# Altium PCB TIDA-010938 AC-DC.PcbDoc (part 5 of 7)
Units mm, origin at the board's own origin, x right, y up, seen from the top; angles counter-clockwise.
Board outline 275 x 170 mm, 4 copper layers (Top Layer, Layer 1, Layer 2, Bottom Layer), stack 1.787 mm thick; 711 components, 426 nets, 2196 pads, 1444 vias.
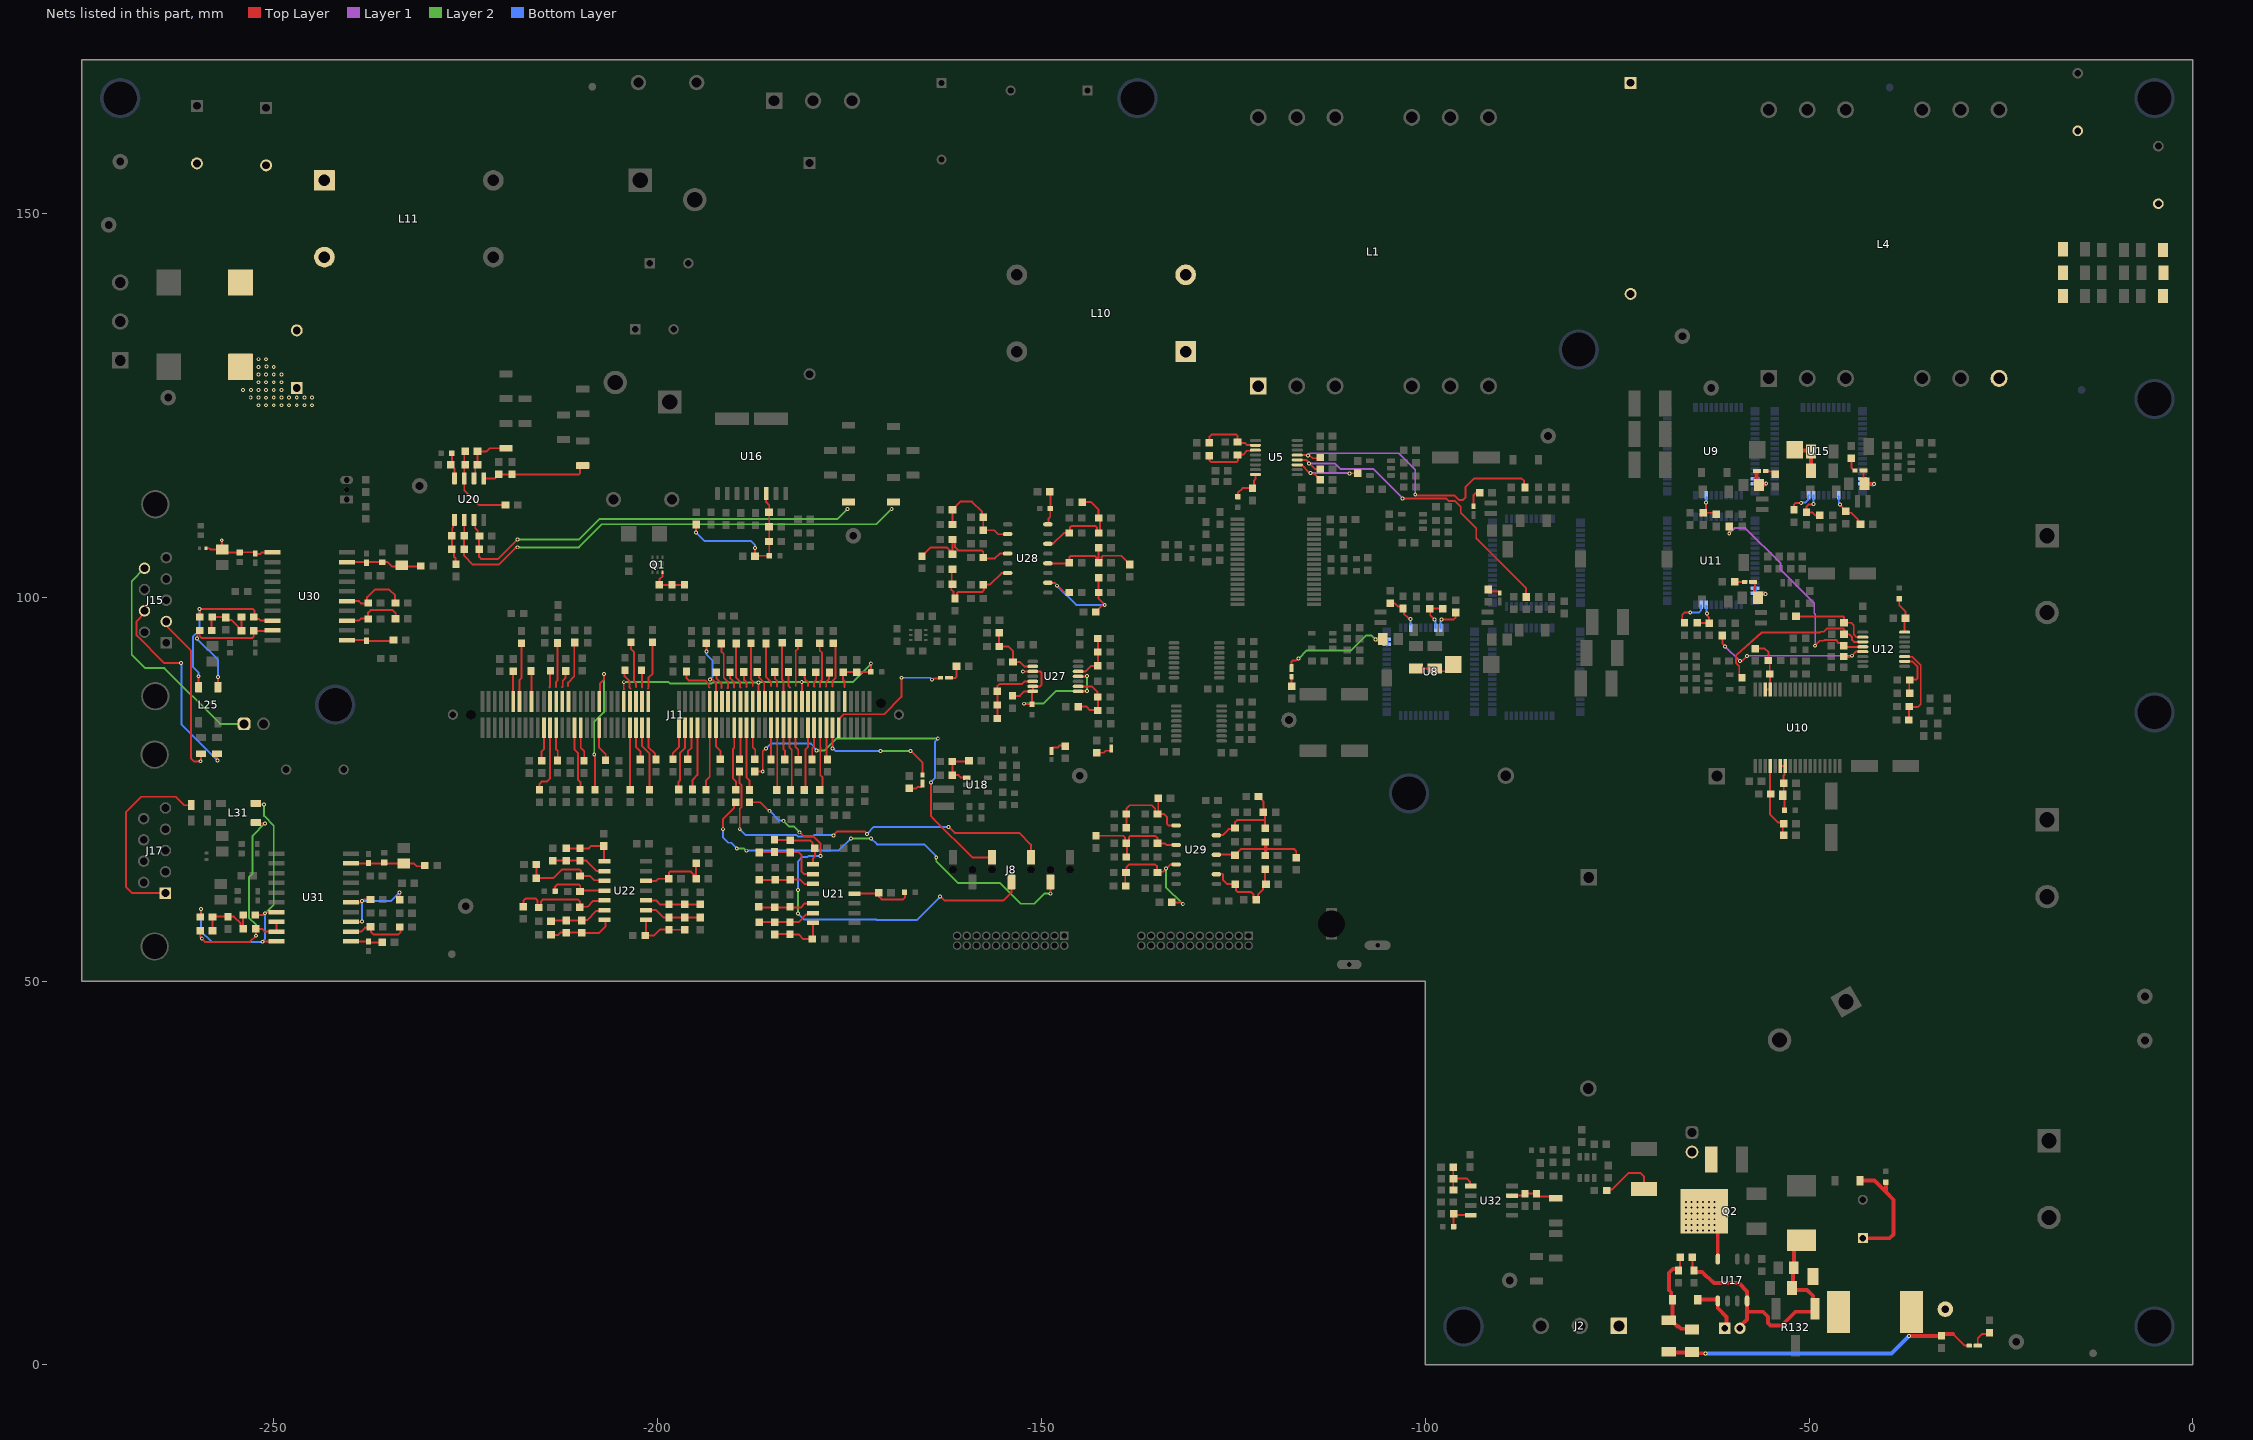
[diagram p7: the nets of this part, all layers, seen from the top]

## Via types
v1: diameter 0.508, hole 0.254, Top Layer to Bottom Layer, tented both sides, 1436 vias
v2: diameter 0.508, hole 0.254, Top Layer to Bottom Layer, 6 vias
v3: diameter 0.5, hole 0.2, Top Layer to Bottom Layer, 2 vias

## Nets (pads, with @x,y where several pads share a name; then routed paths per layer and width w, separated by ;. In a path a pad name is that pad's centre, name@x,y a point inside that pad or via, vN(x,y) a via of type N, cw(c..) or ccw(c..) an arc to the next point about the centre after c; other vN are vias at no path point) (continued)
NetC33_2: C33.2 R29.1 U5.3 | length 10
  Top Layer w0.25: U5.3@-116.675,117.248 -116.113,117.248 -115.095,116.23 -114.982,116.23 v1(-114.933,116.18) ; v1@-114.95,116.163 -114.918,116.131 -114.531,116.131 C33.2@-113.65,115.25 ; v1@-109.75,116.05 -109.65,116.15 R29.1@-108.8,116.15
  Layer 1 w0.25: v1(-114.933,116.18) -114.905,116.153 -109.878,116.153 v1(-109.85,116.125)
NetC34_2: C34.2 R27.1 U5.4 | length 40.7
  Top Layer w0.25: U5.4@-116.675,117.883 -115.533,117.883 -114.375,116.725 -114,116.725 C34.2@-113.9,116.625 ; v1(-102.975,112.875) -102.946,112.846 -97.246,112.846 -96.95,112.55 -96.127,112.55 -95.371,111.794 -95.371,110.971 -93.35,108.95 -93.35,107.675 -86.85,101.175 R27.1@-86.85,100.025
  Layer 1 w0.25: v1(-115.15,117.4) -111.723,117.4 -111.044,116.721 -110.606,116.721 -110.602,116.725 -106.775,116.725 -102.975,112.925 v1(-102.975,112.875)
NetC35_2: C35.2 R25.1 U5.5 | length 38.8
  Top Layer w0.25: U5.5@-116.675,118.518 -115.093,118.518 -114.675,118.1 -113.85,118.1 C35.2@-113.825,118.075 ; v1(-101.3,113.375) -101.23,113.375 -101.101,113.246 -96.18,113.246 -95.605,112.671 -95.081,112.671 -94.771,112.981 -94.771,114.329 -93.65,115.45 -87.425,115.45 -87.125,115.15 -87.125,114.275 R25.1@-86.975,114.125
  Layer 1 w0.25: v1(-115.25,118.475) -114.975,118.75 -103.45,118.75 -101.3,116.6 v1(-101.3,113.375)
NetC38_1: C38.1 FB3.2 U5.16 | length 4.6
  Top Layer w0.25: FB3.2@-124.4,113.1 -124.4,113.6 -123.8,114.2 C38.1@-122.5,114.2 -122.3,114.4 -122.3,115.2 -122.125,115.375 -122.125,115.525 U5.16@-122.125,115.978
NetC41_2: C41.2 R22.2 U5.11 | length 7.3
  Top Layer w0.25: R22.2@-128.1,118.2 -128.1,117.8 -127.925,117.625 -124.546,117.625 -124.4,117.771 -124.4,118.525 -124.352,118.574 -123.721,118.574 -123.22,119.075 U5.11@-122.35,119.075
NetC42_2: C42.2 R20.2 U5.10 | length 7.4
  Top Layer w0.25: R20.2@-128.125,120.45 -128.125,120.875 -127.825,121.175 -124.596,121.175 -124.45,121.029 C42.2@-124.45,120.225 ; C42.2@-124.35,120.075 -123.45,120.075 -123.191,119.816 -122.154,119.816 U5.10@-122.125,119.788
NetC45_1: C45.1 R109.1 R118.2 U20.3 | length 55.9
  Top Layer w0.25: U20.3@-223.915,110.075 -223.75,109.91 -223.75,109 -223.429,108.679 -223.429,108.104 -223.25,107.925 C45.1@-223.25,106.25 -223.25,105.25 -223,105 -220.75,105 v1(-218.25,107.5)
  Layer 2 w0.25: v1(-218.25,107.5) -210.25,107.5 -207.547,110.203 -176.547,110.203 v1(-175.25,111.5)
NetC50_2: C50.2 U8.51 | length 3.8
  Top Layer w0.25: v1(-97.875,97.1) -96.3,97.1 -96.05,97.35 -96.05,98.025 C50.2@-96.075,98.05
  Bottom Layer w0.25: U8.51@-98.008,96 -98.008,96.897 -97.875,97.03 v1(-97.875,97.1)
NetC51_2: C51.2 R35.2 U8.45 | length 4.5
  Top Layer w0.25: R35.2@-104.575,99.225 -104.525,99.175 -103.925,99.175 -103.575,98.825 -103.575,98.8 -103.225,98.8 C51.2@-103,98.575 ; C51.2@-102.9,98.525 -102.775,98.4 -102.775,97.85 -102.175,97.25 -102.07,97.25 -102.019,97.199 -101.976,97.199 v1@-101.925,97.25
  Bottom Layer w0.25: U8.45@-101.925,96.425 -101.9,96.45 v1(-101.9,97.15)
NetC53_2: C53.2 R40.2 U8.50 | length 4.6
  Top Layer w0.25: v1@-98.775,97.125 -98.8,97.125 -99.35,97.675 -99.35,98.45 R40.2@-99.4,98.5 C53.2@-97.7,98.5 -97.65,98.5 C53.2@-97.6,98.55
  Bottom Layer w0.25: v1@-98.75,97.075 -98.75,97.005 -98.658,96.913 U8.50@-98.658,96
  other v1: -98.775,97.1
NetC54_1: C54.1 D25.1 U8.40 U8.41 | length 16.2
  Top Layer w0.25: D25.1@-117.4,90.77 -117.4,91.646 -117.275,91.771 -116.799,91.771 -116.57,92 v1(-116.5,92)
  Top Layer w0.5: v1@-106.425,94.525 -106.4,94.55 C54.1@-105.541,94.55 C54.1@-105.241,94.55
  Layer 2 w0.25: v1(-116.5,92) -115.429,93.071 -109.646,93.071 -107.717,95 -106.975,95 v1(-106.475,94.5)
  Bottom Layer w0.5: v1@-106.325,94.5 U8.41@-105.343,94.5 ; U8.40@-105.018,93.85 U8.41@-105.018,94.475
NetC55_1: C55.1 FB11.2 U27.1 U27.4 U27.10 U27.13 U27.14 | length 24.3
  Top Layer w0.25: C55.1@-153.76,87.143 -152.807,87.143 -152.217,87.733 -151.592,87.733 U27.14@-151.575,87.75 ; v1@-152.425,90.3 -152.392,90.333 -150.146,90.333 -150,90.187 -150,88.529 -150.146,88.383 U27.13@-151.119,88.383 U27.14@-151.119,87.733 -151.125,87.733 -151.217,87.641 FB11.2@-151.217,86.167 ; v1@-152.25,86.05 -152.235,86.065 FB11.2@-151.217,86.065 ; U27.1@-145.219,87.733 -145.211,87.725 v1@-144.075,87.725 ; U27.4@-145.219,89.683 -144.058,89.683 v1@-144.05,89.675
  Layer 2 w0.25: v1(-152.275,86.125) -149.748,86.125 -148.073,87.8 v1(-144.075,87.8) ; v1@-144.1,87.7 -144.062,87.738 -144.062,89.713 v1(-144.05,89.725)
  other v1: -152.425,90.325
NetC60_2: C60.2 R44.2 U9.50 | length 4.3
  Top Layer w0.25: C60.2@-63.9,111.2 -63.625,111.2 -63.45,111.375 v1@-63.45,112.2 ; v1@-63.525,112.25 v1@-63.462,112.188 ; C60.2@-63.5,110.7 C60.2@-63.8,111 -62.4,111 R44.2@-62.2,110.8
  Bottom Layer w0.25: v1@-63.37,112.3 -63.378,112.307 -63.378,112.922 U9.50@-63.3,113
  other v1: -63.45,112.325
NetC61_1: C61.1 D26.1 U9.40 U9.41 | length 5
  Top Layer w0.5: D26.1@-56.8,116.4 -56.84,116.4 -56.84,114.795 -56.909,114.725 -56.859,114.675 -55.802,114.675 -55.677,114.8 v1@-55.675,114.8
  Bottom Layer w0.5: U9.41@-57.025,114.775 -55.75,114.775 v1@-55.7,114.725 ; U9.40@-57.025,115.425 -57,115.425 -56.975,115.4 U9.41@-56.975,114.875
  other v1: -55.575,114.8
NetC64_2: C64.2 C67.1 FB4.2 U10.6 U10.7 | length 6.6
  Top Layer w0.25: U10.6@-53.775,78.025 -53.225,78.025 U10.7@-53.175,77.975 ; C64.2@-53.425,74.2 -53.2,73.975 FB4.2@-53.2,72.25 ; C67.1@-53.325,75.75 -53.325,76.75 -53.175,76.9 U10.7@-53.175,77.975 ; C64.2@-53.3,74.2 C67.1@-53.3,75.75 ; U10.7@-53.125,78.025 U10.7@-53.175,77.975
NetC66_1: C66.1 R45.2 R49.1 U10.33 U10.34 | length 7.2
  Top Layer w0.25: R49.1@-57,93.3 -55.775,93.3 -55.275,92.8 R45.2@-55.275,91.9 ; U10.34@-55.725,87.975 U10.33@-55.175,87.975 ; R45.2@-55.3,91.675 -55.125,91.5 C66.1@-55.125,90 ; U10.33@-55.075,87.975 C66.1@-55.075,90
NetC68_2: C68.2 R46.2 R48.2 U10.4 | length 10.1
  Top Layer w0.25: U10.4@-55.075,78.025 -55.075,74.35 -55.075,71.675 -54.029,70.629 -53.554,70.629 R46.2@-53.425,70.499 ; R48.2@-53.425,68.95 -53.425,70.375 R46.2@-53.325,70.475
NetC70_2: C70.2 U11.51 | length 4.4
  Top Layer w0.25: C70.2@-66.525,96.65 -66.525,97.725 -66.25,98 -65.55,98 v1@-65.5,98.05
  Bottom Layer w0.25: v1(-65.475,98) -64.375,98 -64.075,98.3 -64.075,98.9 U11.51@-64.05,98.925
NetC72_2: C72.2 R60.2 U11.50 | length 4.1
  Top Layer w0.25: C72.2@-64.775,96.65 R60.2@-63.05,96.65 ; v1(-63.3,97.875) -63.275,97.85 -63.275,97.6 -63.05,97.375 R60.2@-63.05,96.675
  Bottom Layer w0.25: U11.50@-63.425,98.875 -63.343,98.793 -63.343,97.918 v1(-63.3,97.875)
NetC73_1: C73.1 D27.1 U11.40 U11.41 | length 4.1
  Top Layer w0.25: D27.1@-57.03,102 -57.03,100.73 C73.1@-57,100.7
  Top Layer w0.5: C73.1@-56.859,100.425 v1(-55.7,100.425)
  Bottom Layer w0.5: U11.41@-57.025,100.6 U11.40@-57.025,101.175 ; U11.41@-56.7,100.5 -55.777,100.5 -55.702,100.425 v1(-55.7,100.425)
NetC74_2: C74.2 R36.2 R110.1 U32.3 | length 5.7
  Top Layer w0.25: U32.3@-88.606,22.104 U32.3@-88.675,22.035 -87.265,22.035 C74.2@-87,22.3 R110.1@-85.5,22.3 -85.5,22.275 -85.15,21.925 -83.825,21.925 R36.2@-83.5,21.6
NetC75_1: C75.1 R124.2 R130.2 U20.6 | length 7.6
  Top Layer w0.25: U20.6@-223.915,115.475 -223.75,115.64 -223.75,116.95 R130.2@-223.45,117.25 C75.1@-223.45,119 -222.25,119 -221.85,119.4 R124.2@-219.75,119.4
NetC75_2: C75.2 R120.1 R130.1 U20.7 | length 11.3
  Top Layer w0.25: C75.2@-225.185,119 U20.7@-225.185,115.475 -225.185,113.935 -223.25,112 R120.1@-219.8,112
NetC77_2: C77.2 R59.1 U12.5 | length 21.7
  Top Layer w0.25: R59.1@-61.3,95 -61.3,93.971 v1@-60.929,93.6 ; v1@-59.025,91.675 -58.75,91.675 v1(-58.075,92.35) ; C77.2@-45.375,92.225 -44.672,92.225 -44.522,92.375 v1(-44.425,92.375) -43.895,92.905 U12.5@-43,92.905
  Layer 1 w0.25: v1@-61,93.575 v1(-60.95,93.575) -60.9,93.575 -59.025,91.7 v1(-58.975,91.7) ; v1@-57.975,92.375 -44.525,92.375 v1@-44.5,92.4
NetC78_2: C78.2 R62.1 U12.4 | length 28.8
  Top Layer w0.25: v1(-60.4,108.3) R62.1@-60.4,109.2 ; v1@-49.15,93.775 -48.596,94.329 -48.073,94.329 -47.977,94.425 -46.486,94.425 -46.325,94.264 -46.325,94.17 -46.179,94.023 -45.848,94.023 -45.35,93.525 U12.4@-43.3,93.525
  Layer 1 w0.25: v1(-60.4,108.3) -59.7,109 -58.3,109 -53.7,104.4 -53.7,103.566 -49.325,99.191 -49.325,97.925 -49.2,97.8 v1@-49.2,93.766
  other v1: -49.25,93.675
NetC79_2: C79.2 R64.1 U12.3 | length 21.7
  Top Layer w0.25: R64.1@-59,89.7 -59.1,89.8 -59.1,91 -59.504,91.404 -59.504,91.919 -59.5,91.923 -59.5,92.3 -59.499,92.401 -59.423,92.477 -56.194,95.4 -48.6,95.4 -48.5,95.5 -48.089,95.5 -47.664,95.925 -46.436,95.925 -45.571,95.925 -45.4,95.754 -45.4,95.225 C79.2@-45.45,95.175 ; C79.2@-45.322,95.047 C79.2@-45.45,95.175 ; -44.125,94.175 -44.419,94.469 -44.419,94.819 -44.775,95.175 C79.2@-45.45,95.175 ; -44.106,94.179 -43.654,94.179 U12.3@-43.625,94.15
NetC80_2: C80.2 R66.1 U12.2 | length 10.4
  Top Layer w0.25: R66.1@-51.7,97.5 -45.55,97.5 -45.451,97.401 -45.451,96.701 C80.2@-45.3,96.55 ; C80.2@-45.3,96.675 -44.475,96.675 -44.175,96.375 -44.175,95.15 -43.839,94.814 -43.561,94.814 U12.2@-43.55,94.825
NetC81_1: C81.1 R129.2 R131.2 U20.2 | length 63.9
  Top Layer w0.25: U20.2@-225.185,110.075 -225.185,108.015 R131.2@-225.2,108 C81.1@-225.2,106.25 -225.2,105.396 -224.054,104.25 -220.684,104.25 -218.484,106.451 -218.299,106.451 v1(-218.25,106.5)
  Layer 2 w0.25: v1(-218.25,106.5) -210.25,106.5 -207.25,109.5 -171.5,109.5 v1(-169.5,111.5)
NetC81_2: C81.2 R121.1 R131.1 U20.1 | length 6.1
  Top Layer w0.25: U20.1@-226.455,110.075 -226.63,109.9 -226.63,109.12 -226.75,109 -226.75,108.05 R131.1@-226.8,108 C81.2@-226.8,106.25 -226.5,105.95 -226.5,105.25 -226.3,105.05 -226.3,104.35 R121.1@-226.25,104.3
NetC84_1: C84.1 FB5.2 U12.16 | length 4.4
  Top Layer w0.25: FB5.2@-38.25,99.8 -38.25,98.95 -37.45,98.15 C84.1@-37.45,97.65 ; U12.16@-37.5,95.4 -37.55,95.45 -37.55,97.15 C84.1@-37.45,97.25
NetC86_2: C86.2 R56.2 U12.11 | length 11.2
  Top Layer w0.25: U12.11@-37.55,92.27 -37.521,92.241 -36.576,92.241 -35.45,91.116 -35.45,86.025 -35.775,85.7 -36.825,85.7 C86.2@-36.975,85.55 ; R56.2@-37,84 -37,85.8 C86.2@-36.975,85.825
NetC87_2: C87.2 R54.2 U12.10 | length 6.5
  Top Layer w0.25: U12.10@-37.55,91.635 -36.535,91.635 -35.85,90.95 -35.85,89.446 -35.996,89.3 C87.2@-36.975,89.3 ; R54.2@-36.95,87.35 -36.95,89.15 C87.2@-36.9,89.2
NetC93_2: C93.2 R38.2 R252.2 U27.2 | length 7.5
  Top Layer w0.25: U27.2@-145.219,88.383 -143.433,88.383 -142.7,87.65 -142.7,87.275 R252.2@-142.675,87.25 ; C93.2@-145.21,85.738 -144.113,85.738 -143.675,85.3 -142.925,85.3 R38.2@-142.9,85.275 ; R252.2@-142.646,87.008 -142.646,85.271 R38.2@-142.625,85.25
NetC95_2: C95.2 U15.51 | length 3.9
  Top Layer w0.152: v1@-51.093,112.207 v1(-51.025,112.275)
  Top Layer w0.25: C95.2@-51.975,111.075 -51.95,111.1 -51.95,112.075 -51.75,112.275 -51.075,112.275 v1@-51.05,112.3
  Bottom Layer w0.152: v1(-51.025,112.275) v1@-51.007,112.293
  Bottom Layer w0.25: v1@-51.05,112.25 -50.976,112.324 -50.476,112.324 -50.135,112.666 -50.135,113.175 U15.51@-50.035,113.275
NetC96_2: C96.2 R69.2 U15.45 | length 5.3
  Top Layer w0.25: v1(-45.95,112.05) -45.95,111.98 -45.373,111.404 -45.373,111.05 -45.348,111.025 C96.2@-45.3,111.025 ; C96.2@-45.225,111.175 -45.05,111 -44.5,111 -43.653,110.153 -43.653,109.85 -43.303,109.5 R69.2@-43.3,109.5
  Bottom Layer w0.152: U15.45@-46.225,113.125 U15.45@-46.213,113.113
  Bottom Layer w0.25: U15.45@-46.2,113.125 -46.135,113.06 -46.135,112.305 -45.95,112.12 v1(-45.95,112.05)
NetC97_2: C97.2 R74.2 U15.50 | length 5
  Top Layer w0.152: R74.2@-49.024,110.425 -49,110.449 R74.2@-49,110.475
  Top Layer w0.25: v1@-49.45,112.15 -49.504,112.096 -50.054,112.096 -50.325,111.825 C97.2@-50.325,111.05 -49.6,111.05 -49.2,110.65 -48.65,110.65 R74.2@-48.625,110.625
  Bottom Layer w0.25: U15.50@-49.385,113.275 -49.405,113.255 -49.405,112.08 v1@-49.375,112.05
  other v1: -49.425,112.125
NetC99_1: C99.1 D28.1 U15.40 U15.41 | length 4.7
  Top Layer w0.25: C99.1@-42.9,115.1 D28.1@-42.9,116.5
  Top Layer w0.5: C99.1@-42.784,114.775 -41.525,114.775 v1@-41.5,114.8
  Bottom Layer w0.5: U15.40@-43.025,115.4 U15.41@-43.025,114.775 -41.8,114.775 v1@-41.725,114.7
  other v1: -41.55,114.75
NetC100_2: C100.2 R67.2 R255.2 U27.5 | length 6.3
  Top Layer w0.25: U27.5@-145.219,90.333 -144.242,90.333 -143.55,91.025 R255.2@-142.725,91.025 ; R255.2@-142.646,91.072 C100.2@-142.646,92.85 R67.2@-142.646,94.628
NetC101_2: C101.2 R72.2 R256.2 U27.9 | length 7.5
  Top Layer w0.25: C101.2@-155.55,93.875 -155.55,95.302 R72.2@-155.487,95.365 ; C101.2@-155.487,93.587 -154.312,93.587 -153.725,93 R256.2@-153.725,91.555 ; R256.2@-153.709,91.555 -152.777,91.555 -152.205,90.983 -151.458,90.983 U27.9@-151.45,90.975
NetC103_1: C103.1 C244.1 L4.6 L10.4 R291.1 R326.1 R327.1
NetC103_2: C103.2 C243.2 L1.1 L10.1 R77.2 R79.2 R80.2
NetC109_1: C109.1 C110.1 C111.1 FB6.2 R84.1 R85.1 U16.8 | length 20.9
  Top Layer w0.25: R84.1@-194.978,109.479 -194.978,108.478 v1@-194.975,108.475 ; v1@-187.3,106.4 -187.308,106.392 R85.1@-187.308,105.34 -187.248,105.4 -185.675,105.4 -185.6,105.325 FB6.2@-185.6,105.25 ; U16.8@-185.845,113.516 -185.875,113.486 -185.875,112.4 -185.45,111.975 -185.45,105.45 FB6.2@-185.525,105.375
  Bottom Layer w0.25: v1(-195,108.45) -193.85,107.3 -187.8,107.3 -187.325,106.825 v1@-187.325,106.575
  other v1: -187.325,106.425
NetC114_1: C114.1 Q1.3 R89.2 R90.1 | length 5.1
  Top Layer w0.25: C114.1@-199.75,101.6 R90.1@-198.125,101.6 R89.2@-196.5,101.6 R89.2@-196.4,101.6 ; C114.1@-199.75,101.675 -199.725,101.7 -199.725,102.375 -199.35,102.75 Q1.3@-199.35,103.275
NetC116_1: C116.1 D14.1 U17.1 | length 6.7
  Top Layer w0.5: D14.1@-64.399,8.5 -61.935,8.5 U17.1@-61.889,8.454 ; U17.1@-61.889,8.327 -61.889,7.389 -60.75,6.25 -60.75,5 C116.1@-61,4.75
NetC116_2: C116.2 C117.2 D20.1 L13.1 R95.1 R97.2 R98.2 R132.1 TP23.1 U17.4 | length 37.9
  Top Layer w0.25: C117.2@-65.2,14 -65.2,12.3 R95.1@-65,12.1
  Top Layer w0.5: R95.1@-65.1,12.1 -63.93,12.1 -63.783,11.954 -63.76,11.931 ccw(c-61.889,13.352) -63.071,11.321 -63.027,11.277 -62.4,10.65 -59.15,10.65 -58.079,9.579 U17.4@-58.079,8.327 -58.079,6.915 -58.079,6.012 ; C116.2@-59,4.75 C116.2@-59,4.971 ; C116.2@-59,5.021 -58.044,5.977 ; -58.079,6.821 -57.985,6.915 -55.99,6.915 -55.346,6.271 -55.346,5.443 -55.023,5.12 -53.557,5.12 -51.762,6.915 -49.21,6.915 -49.5,7.205 -49.5,9 -50.25,9.75 -52.2,9.75 -52.092,9.858 -52.092,12.392 -51.984,12.5 -51.984,14.947 D20.1@-51,15.931
NetC117_1: C117.1 D14.2 D15.1 R93.2 R94.1 | length 13.1
  Top Layer w0.25: R93.2@-67,12.5 -66.975,12.5 -66.8,12.675 C117.1@-66.8,14
  Top Layer w0.5: D15.1@-68.25,5.79 D15.1@-68.145,5.79 ; R93.2@-67,12.5 -67.75,12.5 -68.25,12 -68.25,9.75 -67.952,9.452 -67.952,8.677 D14.2@-67.775,8.5 -67.775,6.16 D15.1@-68.145,5.79 ; R94.1@-65.25,4.7 -66.7,4.7 -67,5 -67.135,5 -67.925,5.79 D15.1@-68.145,5.79
NetC118_1: C118.1 C119.1 D15.2 D16.2 D19.1 FB15.1 L13.2 R94.2 TP20.1 | length 56.4
  Top Layer w0.25: -31.25,4 -29.75,2.5 D16.2@-29.145,2.5
  Top Layer w0.5: D15.2@-68.25,1.71 -68.153,1.613 -65.437,1.613 -65.25,1.8 -64.952,1.502 -63.502,1.502 v1(-63.5,1.5) ; D19.1@-43.362,24 -41.5,24 -40,22.5 ; C118.1@-43,16.5 -39.5,16.5 -39,17 -39,21.5 -40,22.5 ; FB15.1@-40,23.8 -40,22.5 ; v1(-37,3.75) -36.998,3.752 -32.798,3.752 C119.1@-32.75,3.8 -32.55,4 -31.25,4
  Bottom Layer w0.5: v1(-63.5,1.5) -39.25,1.5 v1(-37,3.75)
NetC127_2: C127.2 R104.2 R107.2 U18.1 | length 5.6
  Top Layer w0.25: U18.1@-160,76.525 -160.525,76.525 -160.819,76.819 C127.2@-161.597,76.819 R107.2@-161.597,78.597 -159.578,78.597 R104.2@-159.55,78.625
NetC128_2: C128.2 FB12.2 U32.8 | length 3.5
  Top Layer w0.25: FB12.2@-96.3,18 C128.2@-96.3,19.675 -96.12,19.495 -94.545,19.495 U32.8@-94.525,19.475
NetC129_1: C129.1 R108.1 R113.2 U20.5 | length 14
  Top Layer w0.25: U20.5@-222.645,115.475 -221.175,115.475 -220.65,116 R108.1@-218.95,116 -210.25,116 -210.104,116.146 -210.104,116.825 -209.779,117.15 R113.2@-209.75,117.15
NetC139_2: C139.2 R133.2 R135.1 U32.5 | length 5.8
  Top Layer w0.25: R133.2@-96.35,25.75 -96.35,22.975 C139.2@-96.225,22.85 ; R135.1@-96.325,24.25 -94.55,24.25 -94.175,23.875 -94.175,23.475 U32.5@-94.1,23.4
NetC141_2: C141.2 FB7.2 U21.4 | length 7.8
  Top Layer w0.25: U21.4@-174.347,61.387 -171.463,61.387 C141.2@-171.45,61.4 ; C141.2@-171.195,61.512 -171.15,61.467 -171.15,60.946 -170.829,60.625 -168.025,60.625 -167.75,60.9 -167.75,61.5 FB7.2@-167.725,61.525
NetC142_2: C142.2 FB8.2 U22.4 | length 7.6
  Top Layer w0.25: FB8.2@-213.244,61.65 -213.35,61.756 -213.35,62.3 -213.075,62.575 -210.25,62.575 -210.075,62.4 C142.2@-210.075,61.975 ; C142.2@-210.096,61.65 -209.971,61.775 -207.2,61.775 U22.4@-207.175,61.8
NetC143_2: C143.2 R136.1 R139.2 U22.3 | length 11.3
  Top Layer w0.25: R136.1@-215.797,63.395 -213.589,63.395 -212.433,64.55 -210.175,64.55 -210,64.375 C143.2@-210,63.925 ; R139.2@-215.797,65.173 -215.775,65.151 R136.1@-215.775,63.625 ; C143.2@-210.096,63.682 -208.832,63.682 -208.275,63.125 -207.425,63.125 U22.3@-207.4,63.15
NetC148_1: C148.1 R143.2 R145.2 U22.2 | length 7
  Top Layer w0.25: R143.2@-213.657,65.676 -213.656,65.675 C148.1@-210.225,65.675 ; C148.1@-210.101,65.676 -209.276,65.676 -207.925,64.325 U22.2@-207.125,64.325
NetC148_2: C148.2 R141.1 R145.1 U22.1 | length 6.7
  Top Layer w0.25: R145.1@-211.879,67.276 -211.853,67.25 C148.2@-210.101,67.25 ; C148.2@-210.101,67.276 -208.949,67.276 -208.625,67.6 -207.25,67.6 R141.1@-207.125,67.475 ; U22.1@-207,65.775 -206.998,65.777 R141.1@-206.998,67.475
NetC150_1: C150.1 R147.2 R149.1 U22.5 | length 13.1
  Top Layer w0.25: R149.1@-217.5,59.694 -217.475,59.719 -217.475,60.425 -217.15,60.75 -215.875,60.75 -215.65,60.525 -215.65,59.975 R147.2@-215.675,59.95 ; R147.2@-215.325,59.775 -215.175,59.925 -215.175,60.375 -214.925,60.625 -210.375,60.625 -210.1,60.35 C150.1@-210.1,59.925 ; C150.1@-210.134,59.618 -210.077,59.675 -209.125,59.675 -208.35,60.45 -207.3,60.45 U22.5@-207.2,60.55
NetC154_1: C154.1 R153.1 R155.1 U22.6 | length 7.7
  Top Layer w0.25: R153.1@-214.15,57.775 -214.047,57.878 C154.1@-209.88,57.878 -209.834,57.924 -209.176,57.924 -207.975,59.125 U22.6@-206.975,59.125
NetC154_2: C154.2 R151.1 R155.2 U22.7 | length 8.2
  Top Layer w0.25: R151.1@-213.873,56.02 -212.93,56.02 -212.65,56.3 C154.2@-209.95,56.3 ; C154.2@-209.88,56.278 -207.622,56.278 -206.775,57.125 U22.7@-206.775,57.8
NetC155_2: C155.2 R156.1 R159.2 U22.10 | length 7.2
  Top Layer w0.25: U22.10@-201.504,60.505 -200.205,60.505 -199.65,59.95 R159.2@-194.525,59.95
NetC156_1: C156.1 R157.2 R158.1 U21.10 | length 7.2
  Top Layer w0.25: R158.1@-186.769,63.181 -184.737,63.181 -182.856,63.181 C156.1@-182.8,63.125 ; C156.1@-182.675,63.3 -182.575,63.2 -181.425,63.2 -180.882,62.657 U21.10@-179.747,62.657
NetC159_1: C159.1 R162.1 R164.1 U21.9 | length 9.4
  Top Layer w0.25: R162.1@-186.675,66.725 -186.625,66.775 -181.625,66.775 -181.275,66.425 -181.275,64.304 -180.898,63.927 U21.9@-179.747,63.927
NetC159_2: C159.2 R160.1 R164.2 U21.8 | length 8
  Top Layer w0.25: R164.2@-184.77,68.379 -182.996,68.379 C159.2@-182.875,68.5 ; C159.2@-182.705,68.337 -182.669,68.301 -180.101,68.301 -179.804,68.004 -179.804,67.604 R160.1@-179.5,67.3 ; U21.8@-179.747,65.197 -179.747,65.978 -179.475,66.25 R160.1@-179.475,67.3
NetC160_1: C160.1 R163.2 R165.2 U22.9 | length 7
  Top Layer w0.25: U22.9@-201.504,59.235 -200.185,59.235 -199.2,58.25 C160.1@-198.95,58.25 ; C160.1@-198.499,58.278 R165.2@-196.467,58.278 R163.2@-194.447,58.278
NetC160_2: C160.2 R161.1 R165.1 U22.8 | length 7.5
  Top Layer w0.25: R161.1@-201.626,55.933 -200.442,55.933 -199.65,56.725 C160.2@-198.425,56.725 ; R161.1@-201.504,55.996 U22.8@-201.504,57.965 ; C160.2@-198.425,56.678 -196.572,56.678 R165.1@-196.475,56.775
NetC162_1: C162.1 R167.2 R168.1 U21.12 | length 7.3
  Top Layer w0.25: R168.1@-186.85,59.625 -186.8,59.575 -181.375,59.575 -180.833,60.117 U21.12@-179.747,60.117
NetC163_2: C163.2 R166.2 R172.1 U22.12 | length 9.4
  Top Layer w0.25: U22.12@-201.504,63.045 -200.18,63.045 -199.9,63.325 -198.8,63.325 C163.2@-198.775,63.3 ; C163.2@-198.537,63.32 -198.537,64.104 -198.391,64.25 -195.65,64.25 -195.275,63.875 R172.1@-195.275,63.675 ; R172.1@-194.981,63.32 -194.981,65.314 R166.2@-194.943,65.352
NetC166_1: C166.1 R171.1 R173.1 U21.13 | length 6.9
  Top Layer w0.25: R171.1@-186.769,57.669 C166.1@-182.819,57.669 ; C166.1@-182.738,57.673 -181.602,57.673 -180.603,58.672 -180.397,58.672 -180.25,58.819 U21.13@-180.25,58.85
NetC166_2: C166.2 R169.1 R173.2 U21.14 | length 7.2
  Top Layer w0.25: R173.2@-184.737,56.069 -184.681,56.125 C166.2@-182.8,56.125 ; C166.2@-182.6,56.075 -181.625,56.075 -181.022,55.472 R169.1@-179.832,55.472 -179.747,55.558 -179.747,57.572 U21.14@-179.8,57.625
NetC181_2: C181.2 C182.1 FB9.2 J11.48 J11.84 J11.98 J11.112 | length 46.1
  Top Layer w0.25: v1(-204.4,88.925) -204.404,88.922 -204.404,88.054 -204.375,88.025 ; v1@-186.875,88.8 -186.875,86.466 J11.84@-186.807,86.398 ; v1@-181.225,88.875 -181.207,88.857 J11.98@-181.207,86.398 ; -175.675,88.3 -175.625,88.35 -175.625,89.025 -175.828,89.228 C182.1@-175.828,90.226 -175.79,90.264 FB9.2@-172.286,90.264 ; v1@-172.225,91.425 -172.21,91.41 FB9.2@-172.21,90.264
  Layer 2 w0.25: v1(-204.4,88.925) -198.545,88.925 -198.366,88.746 -192.981,88.746 -192.852,88.875 v1(-186.875,88.875) -186.826,88.924 -186.643,88.924 -186.618,88.95 -174.55,88.95 v1@-172.1,91.4
  other v1: -181.225,88.95 -172.225,91.35
NetC187_2: C187.2 R238.2 R258.2 U27.12 | length 8.6
  Top Layer w0.25: R238.2@-155.85,84.2 -155.741,84.309 C187.2@-155.741,85.967 R258.2@-155.741,87.745 -155.75,87.755 -155.75,88.375 -155.425,88.7 -152.5,88.7 -152.175,89.025 -151.686,89.025 -151.675,89.036 U27.12@-151.675,89.075
NetC189_2: C189.2 C191.1 C195.1 L8.2 U30.9 | length 9.8
  Top Layer w0.25: U30.9@-240.456,104.572 -235.172,104.572 -234.6,104 -231,104 L8.2@-230.9,104.1
NetC190_2: C190.2 R250.1 R263.2 R308.2 U29.2 | length 12.2
  Top Layer w0.25: R308.2@-138.975,70.15 -138.931,70.194 R263.2@-138.931,71.747 -138.931,72.469 -138.5,72.9 -135.625,72.9 -135.172,72.447 -135.172,72.047 C190.2@-135.15,72.025 ; R250.1@-134.775,73.825 -134.775,71.839 C190.2@-134.867,71.747 -134.028,71.747 -133.625,71.344 -133.625,70.45 -133.45,70.275 -132.825,70.275 U29.2@-132.8,70.25
NetC192_2: C192.2 R251.1 R260.2 R302.2 U28.2 | length 12.5
  Top Layer w0.25: R260.2@-161.7,109.45 -161.585,109.565 R302.2@-161.585,111.405 -160.54,112.45 -159.05,112.45 -157.729,111.129 -157.729,110.579 R251.1@-157.575,110.425 C192.2@-157.575,108.725 -156.175,108.725 -155.65,108.2 -154.625,108.2 U28.2@-154.575,108.15
NetC193_2: C193.2 R248.1 R267.2 R307.2 U29.4 | length 13.9
  Top Layer w0.25: R248.1@-142.9,68.925 -139.359,68.925 -139.096,68.662 -139.096,68.102 R267.2@-138.931,67.937 ; R307.2@-138.825,66.2 -138.825,67.831 R267.2@-138.931,67.937 ; C193.2@-134.867,67.937 -133.937,67.937 -133.725,67.725 -132.939,67.725 -132.889,67.675 U29.4@-132.85,67.675 ; C193.2@-134.85,68.2 -134.875,68.225 -134.875,68.625 -135.125,68.875 -138.454,68.875 -138.6,68.729 -138.6,68.268 R267.2@-138.931,67.937
NetC194_2: C194.2 R249.1 R265.2 R301.2 U28.4 | length 14.9
  Top Layer w0.25: R249.1@-165.55,105.35 -165.55,105.375 -164.425,106.5 -162.3,106.5 -161.855,106.055 -161.585,106.055 R301.2@-161.585,107.522 -161.25,107.187 -161.25,106.5 -160.85,106.1 -157.775,106.1 -157.575,105.9 C194.2@-157.575,105.575 ; C194.2@-157.575,105.169 -157.456,105.05 -156.05,105.05 -155.415,105.685 -154.585,105.685 U28.4@-154.55,105.65
NetC196_2: C196.2 R247.1 R268.2 R300.2 U28.6 | length 12.8
  Top Layer w0.25: R268.2@-161.675,101.697 R300.2@-161.675,103.55 ; R268.2@-161.585,101.697 -161.744,101.539 -161.744,100.994 -161.45,100.7 -161.45,100.025 R247.1@-161.25,99.825 -160.973,100.102 -160.973,100.554 -160.827,100.7 -157.7,100.7 -157.5,100.9 C196.2@-157.5,101.5 ; C196.2@-157.5,101.663 -156.662,101.663 -155.18,103.145 U28.6@-154.4,103.145
NetC197_1: C197.1 L12.2 U30.1 | length 5.9
  Top Layer w0.25: U30.1@-240.456,94.412 C197.1@-237.987,94.412 ; C197.1@-237.916,94.32 -234.555,94.32 L12.2@-234.5,94.375
NetC199_2: C199.2 R246.1 R270.2 R306.2 U29.6 | length 16.9
  Top Layer w0.25: R306.2@-139.075,62.6 -139.075,64.021 R270.2@-138.969,64.127 -138.925,64.171 -138.925,64.85 -138.6,65.175 -135.175,65.175 -134.925,64.925 C199.2@-134.925,64.375 ; C199.2@-134.867,64.127 -134.757,64.237 -134.138,64.237 -133.205,65.17 -132.555,65.17 U29.6@-132.525,65.2 ; R246.1@-133.025,60.25 -131.87,60.25 -131.654,60.034 v1(-131.584,60.034)
  Layer 2 w0.25: v1(-133.775,64.65) -133.775,62.225 v1(-131.584,60.034)
NetC200_2: C200.2 R245.1 R273.2 R299.2 U28.10 | length 15.6
  Top Layer w0.25: U28.10@-149.15,101.875 -148.25,101.875 -147.082,100.707 -146.632,100.707 C200.2@-146.575,100.65 ; R245.1@-142.925,98.075 -142.9,98.075 -142.051,98.924 -141.799,98.924 v1(-141.75,98.974) -141.75,99 -142.543,99.793 R273.2@-142.543,100.602 ; R299.2@-142.543,102.544 -142.543,100.818 R273.2@-142.525,100.8
  Bottom Layer w0.25: v1(-147.975,101.496) -145.479,99 -141.776,99 v1(-141.75,98.974)
NetC201_1: C201.1 FB13.2 U28.16 | length 4.3
  Top Layer w0.25: U28.16@-149.15,109.495 -149.05,109.595 -149.05,110.25 -148.85,110.45 FB13.2@-148.85,111.475 ; C201.1@-148.9,113.723 -148.825,113.648 -148.825,111.625 FB13.2@-148.8,111.6
NetC202_2: C202.2 R244.1 R274.2 R305.2 U29.10 | length 12.1
  Top Layer w0.25: U29.10@-127.2,63.915 -127.143,63.972 -126.471,63.972 -126.325,63.826 -126.325,63.125 -125.85,62.65 -125.12,62.65 -124.95,62.48 C202.2@-124.95,62.475 ; C202.2@-124.745,62.618 -124.675,62.548 -124.675,61.8 -124.45,61.575 -122.681,61.575 -122.368,61.262 -122.368,60.693 -122.15,60.475 -121.781,60.844 -121.781,61.302 -121.11,61.973 -121.11,62.253 -120.76,62.603 R274.2@-120.735,62.603 ; R305.2@-120.849,64.566 -120.849,62.953 -120.771,62.875 R274.2@-120.7,62.875
NetC204_2: C204.2 R243.1 R276.2 R298.2 U28.12 | length 14.8
  Top Layer w0.25: U28.12@-149.15,104.415 C204.2@-146.353,104.415 ; C204.2@-146.353,104.487 -146.353,105.229 -146.207,105.375 -143.05,105.375 -142.85,105.175 -142.85,104.7 R276.2@-142.825,104.675 ; R298.2@-142.543,106.427 R276.2@-142.543,104.485 -142.525,104.485 -142.293,104.717 -142.286,104.717 -142.168,104.835 -142.168,105.232 -142,105.4 -139.6,105.4 -138.475,104.275 R243.1@-138.475,104.25
NetC206_2: C206.2 R241.1 R281.2 R297.2 U28.14 | length 14.4
  Top Layer w0.25: U28.14@-149.15,106.955 -149.105,107 -148.425,107 -147.082,108.343 -146.38,108.343 C206.2@-146.353,108.37 -146.275,108.448 -146.275,109.1 -146.075,109.3 -142.975,109.3 -142.747,109.072 -142.747,108.572 R281.2@-142.543,108.368 -142.375,108.536 -142.375,110.142 R297.2@-142.543,110.31 -142.543,111.393 -143.525,112.375 R241.1@-144.7,112.375
NetC208_2: C208.2 R242.1 R278.2 R304.2 U29.12 | length 13.4
  Top Layer w0.25: U29.12@-127.2,66.455 -125.055,66.455 C208.2@-125,66.4 ; C208.2@-124.85,66.447 C208.2@-124.783,66.38 -124.758,66.38 -123.938,67.2 -120.775,67.2 -120.75,67.175 -117.05,67.175 -116.8,66.925 R242.1@-116.8,66.075
  Top Layer w0.5: R278.2@-120.849,66.344 -120.775,66.418 -120.775,67.2 -120.775,68.047 R304.2@-120.849,68.122
NetC209_2: C209.2 R240.1 R282.2 R303.2 U29.14 | length 12
  Top Layer w0.25: U29.14@-127.2,68.995 -126.405,68.995 -125.612,69.788 -124.987,69.788 C209.2@-124.85,69.925 ; C209.2@-124.783,69.936 -124.783,70.692 -124.5,70.975 -120.944,70.975 -120.849,70.88 ; R240.1@-121.725,74.025 -121.7,74.025 -121.35,73.675 -121.35,73.65 -121.089,73.389 R303.2@-121.089,72.001 ; R303.2@-120.989,72.001 -120.849,71.861 -120.849,70.975 -120.849,70.88 ; R282.2@-120.849,69.9 -120.849,70.88
NetC210_1: C210.1 C212.2 C213.2 FB18.1 U30.11 | length 9.9
  Top Layer w0.25: FB18.1@-258.852,106.371 -258.371,106.371 -258.2,106.2 -256.925,106.2 C213.2@-256.831,106.106 ; v1@-256.7,107.4 -256.723,107.377 C213.2@-256.723,106.215 -256.334,105.826 C210.1@-254.437,105.826 ; C210.1@-254.075,105.85 -252.25,105.85 -252,105.6 -251.975,105.625 -251.75,105.625 -251.533,105.842 U30.11@-250.156,105.842
  other v1: -256.774,107.417
NetC214_2: C214.2 C215.1 C216.1 L16.2 U31.9 | length 9.8
  Top Layer w0.25: U31.9@-239.92,65.329 -231.754,65.329 -231.375,64.95 L16.2@-230.25,64.95
NetC217_1: C217.1 C220.2 C221.2 R280.1 R287.2 | length 7.7
  Top Layer w0.25: C217.1@-258.125,95.825 -258.125,97.321 C221.2@-258.019,97.427 C220.2@-256.277,97.427 ; C220.2@-256.247,97.349 -256.247,97.324 -255.968,97.045 -255.545,97.045 -254.585,96.085 -254.585,95.995 -254.29,95.7 R280.1@-254.2,95.7 ; R287.2@-254.21,97.423 -254.21,95.995 -254.165,95.95 R280.1@-254.125,95.95
NetC217_2: C217.2 L25.1 R280.2 U30.19 | length 19.4
  Top Layer w0.25: v1@-259.964,94.602 -259.964,95.342 C217.2@-259.657,95.649 -259.657,94.932 -259.4,94.675 -257.303,94.675 -257.301,94.677 -252.802,94.677 -252.6,94.879 -252.6,95.55 R280.2@-252.55,95.6 ; v1@-257.3,89.5 -257.275,89.475 L25.1@-257.275,88.275 ; R280.2@-252.61,95.645 -252.572,95.607 -250.507,95.607 U30.19@-250.5,95.6
  Bottom Layer w0.25: v1(-260,94.6) -257.25,91.85 -257.25,89.65 v1@-257.3,89.6
  other v1: -257.25,89.6
NetC218_2: C218.2 R311.2 U30.3 | length 8.3
  Top Layer w0.25: U30.3@-240.456,96.952 -239.127,96.952 -239.125,96.95 -238.9,96.95 -238.6,97.25 C218.2@-237.7,97.25 ; C218.2@-237.7,97.169 C218.2@-237.7,97.25 ; C218.2@-237.625,97.225 -237.65,97.25 C218.2@-237.7,97.25 ; R311.2@-234.025,97.325 -234.11,97.41 -234.11,97.91 -234.525,98.325 -237.375,98.325 -237.7,98 C218.2@-237.7,97.25
NetC219_2: C219.2 R314.2 U30.5 | length 8.9
  Top Layer w0.25: U30.5@-240.456,99.492 -238.917,99.492 -238.625,99.2 C219.2@-237.8,99.2 ; C219.2@-237.7,99.234 -237.825,99.359 -237.825,100 -236.825,101 -234.975,101 -234.2,100.225 -234.2,99.325 R314.2@-234.15,99.275
NetC221_1: C221.1 L25.2 R287.1 U30.18 | length 22.4
  Top Layer w0.25: v1@-259.8,89.65 -259.775,89.625 L25.2@-259.775,88.275 ; v1(-259.65,98.45) -252.7,98.45 -252.5,98.25 -252.5,97.533 R287.1@-252.61,97.423 -252.326,97.139 -251.889,97.139 -251.702,96.952 U30.18@-250.156,96.952 ; C221.1@-259.619,97.427 v1@-259.619,98.419
  Bottom Layer w0.25: v1@-259.8,89.8 -259.819,89.819 -259.819,90.219 -260.5,90.9 -260.5,94.352 -260.529,94.381 -260.529,94.819 -259.65,95.698 v1(-259.65,98.45)
  other v1: -259.825,89.7
NetC222_1: C222.1 L17.2 U31.1 | length 3.9
  Top Layer w0.25: U31.1@-239.92,55.169 C222.1@-237.794,55.169 ; C222.1@-237.658,55.134 -237.524,55 L17.2@-235.975,55
NetC229_1: C229.1 J7.2 Q2.2 U17.8 | length 3.5
  Top Layer w0.5: U17.8@-61.889,13.777 Q2.2@-61.889,17.239
  other v1: -66.052,17.474 -65.302,17.474 -64.552,17.474 -63.802,17.474 -63.052,17.474 -62.302,17.474 -66.05,18.22 -65.3,18.22 -64.55,18.22 -63.8,18.22 -63.05,18.22 -62.3,18.22 -66.05,18.97 -65.3,18.97 -64.55,18.97 -63.8,18.97 -63.05,18.97 -62.3,18.97 -66.05,19.72 -65.3,19.72 -64.55,19.72 -63.8,19.72 -63.05,19.72 -62.3,19.72 -66.05,20.47 -65.3,20.47 -64.55,20.47 -63.8,20.47 -63.05,20.47 -62.3,20.47 -66.05,21.22 -65.3,21.22 -64.55,21.22 -63.8,21.22 -63.05,21.22 -62.3,21.22
NetC230_2: C230.2 FB14.2 U20.8 | length 3.6
  Top Layer w0.25: FB14.2@-226.8,118.75 -226.8,117.4 C230.2@-226.95,117.25 -226.925,117.25 -226.455,116.78 U20.8@-226.455,115.475
NetC233_1: C233.1 C236.2 C237.2 R288.1 R289.2 | length 8.3
  Top Layer w0.25: C233.1@-257.978,56.566 -257.978,58.222 C237.2@-257.9,58.3 ; C237.2@-257.9,58.4 C236.2@-255.946,58.4 ; C236.2@-255.946,58.382 -255.195,58.382 -254.327,57.514 -254.327,57.002 R288.1@-254.05,56.725 ; R289.2@-253.99,58.598 -253.99,57.165 R288.1@-253.8,56.975
NetC233_2: C233.2 L31.1 R288.2 U31.18 U31.19 | length 29.9
  Top Layer w0.25: C233.2@-259.578,56.566 -259.578,55.722 -258.956,55.1 -253.1,55.1 v1(-252.3,55.9) -252.3,56.47 -252.43,56.6 R288.2@-252.5,56.6 ; R288.2@-252.352,56.82 -252.332,56.8 -251.5,56.8 -251.139,56.439 -250.545,56.439 -250.5,56.484 U31.19@-250.5,56.5 ; L31.1@-252.325,70.65 -252.196,70.521 v1(-251.158,70.521) ; U31.18@-249.62,57.709 -249.62,56.52 U31.19@-249.6,56.5
  Layer 2 w0.25: v1(-252.3,55.9) -252.3,57.3 -253.25,58.25 -253.25,63.5 -252.75,64 -252.75,68.929 v1(-251.158,70.521)
  other v1: -259.374,55.517
NetC234_2: C234.2 R320.2 U31.3 U31.5 | length 13.1
  Top Layer w0.25: U31.3@-239.92,57.709 -238.509,57.709 v1@-238.5,57.7 ; U31.5@-239.92,60.249 -238.599,60.249 -238.198,60.65 -237.525,60.65 R320.2@-237.475,60.6 ; v1@-233.6,61.475 -233.6,60.607 C234.2@-233.59,60.597
  Bottom Layer w0.25: v1(-238.525,57.75) -238.512,57.763 -238.512,60.488 v1@-238.5,60.5 ; v1(-238.5,60.425) -234.725,60.425 v1(-233.6,61.55) v1@-233.6,61.6
NetC235_2: C235.2 R323.2 U31.2 | length 7.9
  Top Layer w0.25: U31.2@-239.92,56.439 -238.614,56.439 -238.1,56.953 R323.2@-237.547,56.953 ; R323.2@-237.404,57.074 -237.325,56.995 -237.325,56.375 -237.025,56.075 -233.75,56.075 -233.475,56.35 C235.2@-233.475,56.8
NetC237_1: C237.1 L31.2 R289.1 U31.17 U31.20 | length 36.6
  Top Layer w0.25: C237.1@-259.578,58.344 -259.5,58.422 v1(-259.5,59.4) ; R289.1@-252.39,58.598 -251.302,58.598 -250.9,59 U31.17@-250.4,59 ; L31.2@-252.325,73.15 -252.175,73 v1(-251.25,73) ; v1@-251.4,55.1 -251.331,55.169 U31.20@-249.62,55.169
  Layer 2 w0.25: v1(-251.25,73) -251.25,71.5 -250,70.25 -250,59.952 v1(-251.123,58.828)
  Bottom Layer w0.25: v1(-259.5,59.4) -259.5,56.5 -258.1,55.1 v1@-251.5,55.1 ; v1@-251.5,55.2 -251.461,55.2 -251.123,55.537 v1(-251.123,58.828)
  other v1: -251.474,55.117
NetD1_2: D1.2 R7.2 R41.2 | length 3.8
  Top Layer w0.25: R41.2@-101.2,90.725 R7.2@-98.75,90.725 ; R7.2@-98.2,90.275 -98.125,90.35 D1.2@-96.9,90.35
NetD4_2: D4.2 R17.2 | length 1.7
  Top Layer w0.25: R17.2@-91.8,101 -91.55,100.75 -90.425,100.75 -90.3,100.625 D4.2@-90.3,100.545
NetD7_2: D7.2 R53.2 R55.2 | length 4.2
  Top Layer w0.5: D7.2@-51.5,119 -51.4,119.1 -49.85,119.1 R55.2@-49.725,118.975 ; R53.2@-49.75,116.475 -49.738,116.488 R55.2@-49.738,118.762
NetD10_2: D10.2 R42.2 | length 2.4
  Top Layer w0.25: D10.2@-93.7,111.845 -93.7,113.3 -93.4,113.6 R42.2@-92.9,113.6
NetD16_1: D16.1 R100.1 | length 2.8
  Top Layer w0.25: D16.1@-28.03,2.5 -28.03,3.47 -27.5,4 -26.7,4 R100.1@-26.5,4.2
NetD17_1: D17.1 R101.2 | length 1.8
  Top Layer w0.25: D17.1@-148.7,80.3 -148.6,80.4 -147.9,80.4 -147.6,80.7 R101.2@-147.1,80.7
NetD18_1: D18.1 R102.2 | length 1.8
  Top Layer w0.25: R102.2@-142.783,79.738 -141.862,79.738 -141.6,80 D18.1@-141.1,80
NetD23_1: D23.1 R70.2 | length 1.8
  Top Layer w0.25: R70.2@-167.2,75.1 -166.3,75.1 -166.1,75.3 -165.6,75.3 D23.1@-165.5,75.4
NetD23_2: D23.2 J11.107 | length 16.7
  Top Layer w0.25: J11.107@-177.207,82.998 -177.204,82.995 -177.204,80.303 v1(-177.2,80.3) ; v1@-167,80 -165.5,78.5 D23.2@-165.5,77
  Layer 2 w0.25: v1(-170.975,79.975) v1(-167.075,79.975) -167.025,79.975 v1@-167,80
  Bottom Layer w0.25: v1(-177.2,80.3) -177.13,80.3 -176.776,79.946 v1@-170.954,79.946
NetD24_1: D24.1 R76.2 | length 2.4
  Top Layer w0.25: D24.1@-162.03,89.5 -161.196,89.5 -161.05,89.646 R76.2@-161.05,91
NetD24_2: D24.2 J11.109 | length 18.4
  Top Layer w0.25: J11.109@-176.407,82.998 -176.407,84.093 -175.75,84.75 -170.5,84.75 -168.25,87 v1(-168.25,89.504) ; v1(-164.25,89.25) -164.18,89.25 -164.023,89.408 -163.237,89.408 D24.2@-163.145,89.5 D24.2@-163.245,89.5
  Bottom Layer w0.25: v1(-168.25,89.504) -164.504,89.504 v1(-164.25,89.25)
NetD25_2: D25.2 R43.2 | length 1.3
  Top Layer w0.25: R43.2@-117.4,88.4 D25.2@-117.4,89.655
NetD26_2: D26.2 R51.2 | length 1.2
  Top Layer w0.25: D26.2@-55.4,116.4 -54.9,116.4 -54.875,116.375 -54.75,116.375 -54.5,116.125 -54.5,116 R51.2@-54.4,116
NetD27_2: D27.2 R52.2 | length 1.6
  Top Layer w0.25: R52.2@-60,102 R52.2@-59.995,102 ; R52.2@-59.7,102 D27.2@-58.145,102
NetD28_2: D28.2 R115.2 | length 1.7
  Top Layer w0.25: R115.2@-44.5,117.9 -44.5,116.885 -44.115,116.5 D28.2@-44.015,116.5
NetF1_1: F1.1 L11.4 R78.2 R82.2
NetF2_1: F2.1 L11.1 R81.2 R82.1
  other v1: -252,125 -251,125 -250,125 -249,125 -248,125 -247,125 -246,125 -245,125 -251.032,125.98 -253,126 -252,126 -250,126 -249,126 -248,126 -247,126 -246,126 -245,126 -254,127 -252.949,126.995 -252,127 -251,127 -250,127 -249,127 -252,128 -251,128 -250,128 -249,128 -252,129 -251,129 -250,129 -249,129 -252,130 -250,130 -250.95,130.051 -251.032,130.994 -252,131
NetJ2_1: J2.1 R1.1 R3.1 | length 7.6
  Top Layer w0.25: R3.1@-76.375,22.7 -76.221,22.854 -75.646,22.854 -73.5,25 -72,25 -71.5,24.5 R1.1@-71.5,22.9
NetJ8_2: J8.2 R57.1 | length 55.3
  Top Layer w0.25: v1@-191.5,69.8 -191.5,71.1 -190.029,72.571 -190.029,73.071 R57.1@-189.8,73.3 ; J8.2@-148.82,62.9 -148.82,61.42 v1@-148.8,61.4
  Layer 2 w0.25: v1(-189.684,67.28) -188.774,67.28 -188.493,67 v1@-188.4,67 ; v1@-174.79,68.574 v1(-172.198,68.574) ; v1(-163.698,66.074) -163.698,65.57 -160.899,62.772 -155.406,62.772 -152.705,60.071 -150.927,60.071 -149.624,61.374 v1(-148.798,61.374)
  Bottom Layer w0.25: v1(-191.498,69.774) -191.498,68.698 -190.814,68.014 -190.417,68.014 v1(-189.684,67.28) ; v1(-188.398,66.974) -188.369,67.003 -176.369,67.003 v1(-174.798,68.574) ; v1@-172.2,68.6 -171.4,67.8 -165.252,67.8 -163.747,66.295 -163.747,66.124 v1(-163.698,66.074)
NetJ8_3: J8.3 R210.1 | length 49.4
  Top Layer w0.25: R210.1@-189.325,77.3 -189.325,75.789 -189.05,75.514 -189.05,72.686 -189.3,72.436 v1@-189.3,69.8 ; v1(-177.098,68.974) -176.572,69.5 -173.024,69.5 v1(-172.698,69.174) ; v1@-162.1,70.1 -161.3,69.3 -152.9,69.3 -151.36,67.76 J8.3@-151.36,66.105
  Bottom Layer w0.25: v1(-189.298,69.774) -188.528,69.004 -181.876,69.004 -181.717,68.845 -179.807,68.845 -179.648,69.004 -177.104,69.004 v1@-177.1,69 ; v1@-172.7,69.2 -171.826,70.074 v1(-162.098,70.074)
NetJ8_4: J8.4 R212.1 | length 54.5
  Top Layer w0.25: R212.1@-188.02,73.291 -186.618,73.291 -185.527,72.2 v1@-185.4,72.2 ; v1(-181.498,69.374) -181.024,68.9 -179.776,68.9 -178.765,67.889 -178.765,66.335 v1@-178.8,66.3 ; v1(-163.2,61) -163.134,61 -162.634,60.5 -154.9,60.5 -153.9,61.5 J8.4@-153.9,62.9
  Layer 2 w0.25: v1(-183.598,70.874) -182.836,70.112 -182.212,70.112 v1@-181.5,69.4 ; v1@-181.7,61.9 -181.698,61.898 v1(-181.698,61.874) v1(-181.698,58.774)
  Bottom Layer w0.25: v1(-185.398,72.174) -184.124,70.9 v1@-183.6,70.9 ; v1(-181.698,58.774) -180.924,58 -171.501,58 -171.443,57.942 -166.258,57.942 v1(-163.2,61) ; v1(-181.698,61.874) -181.698,65.602 -181.136,66.164 -180.456,66.164 -180.346,66.274 v1(-178.798,66.274)
NetJ8_5: J8.5 R214.1 | length 48.6
  Top Layer w0.25: R214.1@-187.325,77.3 v1@-186.3,77.3 ; v1(-186.298,77.274) -186.298,79.902 v1@-185.9,80.3 ; v1(-164.398,75.874) -164.398,71.5 -164,71.102 ; -164,71.1 -164,71.102 ; J8.5@-156.44,66.105 -159.003,66.105 -163.999,71.101
  Layer 2 w0.25: v1(-179.321,80.042) -178.206,80.042 -176.648,81.6 v1@-163.5,81.6
  Bottom Layer w0.25: v1(-185.898,80.274) -185.243,80.929 -180.029,80.929 -179.724,80.624 -179.724,80.515 -179.321,80.112 v1(-179.321,80.042) ; v1@-164.4,75.9 -163.846,76.454 -163.846,81.226 v1(-163.498,81.574)
NetJ11_12: J11.12 R174.1 | length 4
  Top Layer w0.25: J11.12@-218.807,86.398 -218.807,90.393 R174.1@-218.775,90.425
NetJ11_14: J11.14 R175.1 | length 7.7
  Top Layer w0.25: J11.14@-218.007,86.398 -218.007,89.193 -217.7,89.5 R175.1@-217.7,93.95
NetJ11_18: J11.18 R179.1 | length 4
  Top Layer w0.25: R179.1@-216.425,90.35 -216.407,90.332 J11.18@-216.407,86.398
NetJ11_21: J11.21 R183.1 | length 4.5
  Top Layer w0.25: R183.1@-215.125,78.675 -215.125,79.875 -214.807,80.193 J11.21@-214.807,82.998
NetJ11_23: J11.23 R182.1 | length 8.9
  Top Layer w0.25: R182.1@-215.425,75.2 -215.375,75.25 -215.375,75.7 -215.1,75.975 -214.45,75.975 -214.007,76.418 J11.23@-214.007,82.998 ; R182.1@-215.411,74.864 R182.1@-215.375,74.9 R182.1@-215.329,74.946
NetJ11_24: J11.24 R181.2 | length 2.3
  Top Layer w0.25: -214.1,88.225 -214.007,88.318 -214.007,90.368 R181.2@-213.95,90.425
NetJ11_25: J11.25 R184.1 | length 4.5
  Top Layer w0.25: J11.25@-213.207,82.998 -213.207,80.182 -213,79.975 -213,78.9 R184.1@-212.8,78.7 ; R184.1@-212.979,78.489 R184.1@-212.954,78.514
NetJ11_26: J11.26 R180.2 | length 5.8
  Top Layer w0.25: -213.25,88.3 -213.225,88.325 -213.225,88.975 -213.025,89.175 R180.2@-213.025,94.025
NetJ11_28: J11.28 R178.2 | length 2.3
  Top Layer w0.25: -212.425,88.275 -212.35,88.35 -212.35,89.1 -211.975,89.475 R178.2@-211.975,90.375
NetJ11_30: J11.30 R176.2 | length 6
  Top Layer w0.25: -211.65,88.45 -211.65,88.875 -210.85,89.675 -210.85,94.05 R176.2@-210.8,94.1
NetJ11_31: J11.31 R186.2 | length 7.9
  Top Layer w0.25: J11.31@-210.807,82.998 -210.807,80.132 -210.35,79.675 -210.35,76.2 -210.05,75.9 R186.2@-210.05,75.375
NetJ11_33: J11.33 R187.2 | length 4.4
  Top Layer w0.25: J11.33@-210.007,82.998 -210.007,80.382 -209.55,79.925 R187.2@-209.55,78.825
NetJ11_39: J11.39 R189.2 | length 4.4
  Top Layer w0.25: J11.39@-207.607,82.998 -207.607,80.407 -206.75,79.55 R189.2@-206.75,79
NetJ11_40: J11.40 R188.2 | length 19.4
  Top Layer w0.25: R188.2@-208.153,74.916 v1@-208.153,79.403 ; J11.40@-207.607,86.398 -207.482,86.523 -207.482,88.768 -207,89.25 v1(-207,90)
  Layer 2 w0.25: v1(-208.25,79.5) -208.25,83.75 -207,85 v1(-207,90)
NetJ11_49: J11.49 R190.2 | length 8.3
  Top Layer w0.25: R190.2@-203.65,75.025 -203.607,75.068 J11.49@-203.607,82.998 ; R190.2@-203.607,75.057 R190.2@-203.4,74.85
NetJ11_50: J11.50 R194.2 | length 2.7
  Top Layer w0.25: R194.2@-204.25,90.5 -204.3,90.45 -204.3,89.675 -203.65,89.025 -203.65,88.225 -203.55,88.125
NetJ11_51: J11.51 R192.2 | length 4.2
  Top Layer w0.25: J11.51@-202.807,82.998 -202.807,80.457 -202.25,79.9 R192.2@-202.25,79
NetJ11_52: J11.52 R196.2 | length 6.3
  Top Layer w0.25: R196.2@-203.45,94.4 -203.45,93.225 -203.05,92.825 -203.05,89.025 -202.825,88.8 -202.825,88.325
NetJ11_53: J11.53 R198.2 | length 8.3
  Top Layer w0.25: J11.53@-202.007,82.998 -202.007,80.582 -201.025,79.6 R198.2@-201.025,75.075
NetJ11_54: J11.54 R191.1 | length 2.3
  Top Layer w0.25: R191.1@-202.1,90.475 -202.025,90.4 -202.025,88.25
NetJ11_55: J11.55 R199.2 | length 4.5
  Top Layer w0.25: J11.55@-201.207,82.998 -201.207,80.457 -200.329,79.579 -200.329,79.004 R199.2@-200.225,78.9
NetJ11_56: J11.56 R193.1 | length 6.4
  Top Layer w0.25: -201.225,88.125 -201.207,88.143 ; -201.2,88.275 -201.2,89.475 -200.65,90.025 R193.1@-200.65,94.4
NetJ11_57: J11.57 R200.2 | length 4.2
  Top Layer w0.25: R200.2@-198.025,79.15 -198.025,79.675 -197.207,80.493 J11.57@-197.207,82.998
NetJ11_59: J11.59 R201.2 | length 8
  Top Layer w0.25: R201.2@-197.3,75.325 -197.3,75.95 -197.075,76.175 -197.075,79.725 -196.407,80.393 J11.59@-196.407,82.998
NetJ11_61: J11.61 R195.1 | length 4.4
  Top Layer w0.25: R195.1@-196.05,78.825 R195.1@-196.05,78.875 -196.05,79.9 -195.607,80.343 J11.61@-195.607,82.998
NetJ11_63: J11.63 R197.1 | length 8
  Top Layer w0.25: R197.1@-195.516,75.325 -195.516,75.334 -195.45,75.4 -195.45,76.204 -194.807,76.847 J11.63@-194.807,82.998
NetJ11_67: J11.67 R203.2 | length 8.2
  Top Layer w0.25: R203.2@-193.825,75.025 -193.7,75.15 -193.7,76.1 -193.207,76.593 J11.67@-193.207,82.998
NetJ11_68: J11.68 R204.1 | length 4.6
  Top Layer w0.25: R204.1@-196.219,90.326 -196.219,89.419 -195.95,89.15 -193.798,89.15 -193.329,88.681 -193.329,88.329 -193.225,88.225
NetJ11_69: J11.69 R205.2 | length 4.2
  Top Layer w0.25: J11.69@-192.407,82.998 -192.407,80.557 -191.825,79.975 R205.2@-191.825,79.025
NetJ11_70: J11.70 R206.1 | length 8.5
  Top Layer w0.25: v1@-193.65,93 -193.641,93.009 R206.1@-193.641,93.998 ; v1(-193.175,89.3) -193.126,89.251 -192.826,89.251 -192.407,88.832 J11.70@-192.407,86.398
  Layer 1 w0.25: v1(-193.65,92.95) v1@-193.643,92.943
  Bottom Layer w0.25: v1@-193.643,92.943 -193.643,92.568 -192.825,91.75 -192.825,89.65 v1(-193.175,89.3)
NetJ11_72: J11.72 R207.1 | length 2.3
  Top Layer w0.25: R207.1@-192.338,90.226 -192.338,89.438 -191.675,88.775 -191.675,88.175
NetJ11_74: J11.74 R208.1 | length 6.2
  Top Layer w0.25: R208.1@-191.699,93.976 -191.699,92.924 -191.375,92.6 -191.375,89.5 -190.807,88.932 -190.807,88.218 -190.875,88.15
NetJ11_75: J11.75 R57.2 | length 8.3
  Top Layer w0.25: J11.75@-190.007,82.998 -190.007,80.393 -190.2,80.2 -190.2,76.4 -189.8,76 R57.2@-189.8,74.9
NetJ11_76: J11.76 R209.1 | length 2.2
  Top Layer w0.25: R209.1@-190.56,90.226 -190.56,89.435 -190.022,88.897 -190.022,88.278 -190.075,88.225
NetJ11_77: J11.77 R210.2 | length 4
  Top Layer w0.25: J11.77@-189.207,82.998 -189.207,79.157 R210.2@-189.075,79.025
NetJ11_78: J11.78 R211.1 | length 6
  Top Layer w0.25: R211.1@-189.758,93.998 -189.758,89.533 -189.275,89.05 -189.275,88.325 -189.175,88.225
NetJ11_79: J11.79 R212.2 | length 7.9
  Top Layer w0.25: J11.79@-188.407,82.998 -188.407,76.507 -188,76.1 R212.2@-188,75.3
NetJ11_80: J11.80 R213.1 | length 2.1
  Top Layer w0.25: R213.1@-188.782,90.264 -188.725,90.207 -188.725,89.225 -188.4,88.9 -188.4,88.3
NetJ11_81: J11.81 R214.2 | length 4.2
  Top Layer w0.25: J11.81@-187.607,82.998 -187.607,80.484 -187.275,80.152 -187.275,79.125 R214.2@-187.4,79
NetJ11_82: J11.82 R215.1 | length 5.7
  Top Layer w0.25: R215.1@-187.816,93.998 -187.816,89.241 -187.6,89.025 -187.6,88.4
NetJ11_86: J11.86 R216.1 | length 4.3
  Top Layer w0.25: R216.1@-187.004,90.264 -186.785,90.045 -186.785,89.535 -186.105,88.855 -186.105,86.496 J11.86@-186.007,86.398
NetJ11_87: J11.87 R217.2 | length 3.9
  Top Layer w0.25: R217.2@-185.225,79.1 -185.207,79.118 J11.87@-185.207,82.998
NetJ11_88: J11.88 R218.1 | length 5.8
  Top Layer w0.25: R218.1@-185.875,93.975 -185.875,89.6 -185.2,88.925 -185.2,88.425
NetJ11_89: J11.89 R219.2 | length 8
  Top Layer w0.25: R219.2@-184.475,75.075 -184.407,75.143 J11.89@-184.407,82.998
NetJ11_90: J11.90 R220.1 | length 2
  Top Layer w0.25: R220.1@-184.718,90.264 -184.718,89.393 -184.425,89.1 -184.425,88.375
NetJ11_91: J11.91 R221.2 | length 4.1
  Top Layer w0.25: J11.91@-183.607,82.998 -183.607,80.182 -183.4,79.975 R221.2@-183.4,79
NetJ11_92: J11.92 R222.1 | length 7.8
  Top Layer w0.25: J11.92@-183.607,86.398 -183.607,89.102 -183.8,89.295 -183.8,93.775 R222.1@-183.55,94.025
NetJ11_93: J11.93 R223.2 | length 8
  Top Layer w0.25: J11.93@-182.807,82.998 -182.807,80.407 -182.525,80.125 -182.525,75.266 -182.566,75.225 R223.2@-182.65,75.225
NetJ11_94: J11.94 R224.1 | length 2.1
  Top Layer w0.25: R224.1@-182.94,90.264 -182.94,88.405 -182.785,88.25 -182.775,88.25
NetJ11_95: J11.95 R225.2 | length 4.1
  Top Layer w0.25: J11.95@-182.007,82.998 -182.007,80.457 -181.675,80.125 R225.2@-181.675,79.075
NetJ11_96: J11.96 R226.1 | length 5.8
  Top Layer w0.25: -182,88.425 -182,93 -181.704,93.296 -181.704,93.93 R226.1@-181.609,94.025
NetJ11_99: J11.99 R227.2 | length 8.3
  Top Layer w0.25: R227.2@-180.85,74.85 -180.75,74.95 -180.75,80.125 -180.407,80.468 J11.99@-180.407,82.998
NetJ11_100: J11.100 R228.1 | length 2.1
  Top Layer w0.25: R228.1@-181.162,90.226 -180.839,89.903 -180.839,89.544 -180.803,89.508 -180.803,89.298 -180.4,88.895 -180.4,88.4
NetJ11_101: J11.101 R229.2 | length 4
  Top Layer w0.25: R229.2@-179.85,79.1 -179.85,80.325 -179.607,80.568 J11.101@-179.607,82.998
NetJ11_102: J11.102 R230.1 | length 1.9
  Top Layer w0.25: -179.575,88.35 -179.607,88.382 -179.607,88.943 -179.325,89.225 R230.1@-179.325,90.1
NetJ11_103: J11.103 R231.2 | length 8.4
  Top Layer w0.25: R231.2@-178.9,74.975 -178.817,74.975 -178.526,75.266 -178.526,75.386 -178.5,75.412 -178.5,76.527 -178.807,76.834 -178.807,79.917 -178.769,79.955 -178.769,80.393 -178.807,80.431 J11.103@-178.807,82.998
NetJ11_104: J11.104 R232.1 | length 5.9
  Top Layer w0.25: R232.1@-178.876,93.998 -178.876,93.051 -178.575,92.75 -178.575,89.275 -178.825,89.025 -178.825,88.325
NetJ11_105: J11.105 R233.2 | length 3.9
  Top Layer w0.25: J11.105@-178.007,82.998 -178.007,79.207 R233.2@-177.925,79.125
NetJ11_106: J11.106 R234.1 | length 2
  Top Layer w0.25: -178.075,88.375 -178.047,88.375 -178.025,88.397 -178.025,88.975 -177.65,89.35 -177.65,90.144 R234.1@-177.606,90.188
NetJ11_108: J11.108 R236.1 | length 5.9
  Top Layer w0.25: -177.25,88.375 -177.222,88.375 -177.2,88.397 -177.2,89.1 -176.8,89.5 -176.8,93.7 R236.1@-177.098,93.998
NetJ15_2: J15.2 R316.2 | length 21.2
  Top Layer w0.25: J15.2@-263.999,96.838 -263.999,96.261 -260.8,93.062 -260.8,79 -260.4,78.6 v1@-259.7,78.6 ; v1@-259.5,78.8 -259.5,79.575 R316.2@-259.475,79.6
  other v1: -259.523,78.628
NetJ15_7: J15.7 R312.2 | length 26.4
  Top Layer w0.25: J15.7@-266.839,98.223 -266.839,97.885 -267.864,96.86 -267.864,95.029 -264.235,91.4 v1@-262,91.4 ; v1@-257.4,78.7 -257.375,78.725 R312.2@-257.375,79.6
  Bottom Layer w0.25: v1(-262.074,91.417) -262.025,91.367 -262.025,83.43 -257.4,78.805 v1@-257.4,78.8
  other v1: -257.323,78.728
NetJ15_9: J15.9 J16.1 | length 30.3
  Layer 2 w0.25: J15.9@-266.839,103.763 -268.5,102.102 -268.5,92.5 -266.75,90.75 -264.25,90.75 -257,83.5 J16.1@-253.87,83.5
NetJ17_1: J17.1 R325.2 | length 25
  Top Layer w0.25: J17.1@-264.105,61.46 -268.46,61.46 -269.25,62.25 -269.25,72 -267.25,74 -262.75,74 -261.65,72.9 R325.2@-260.75,72.9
